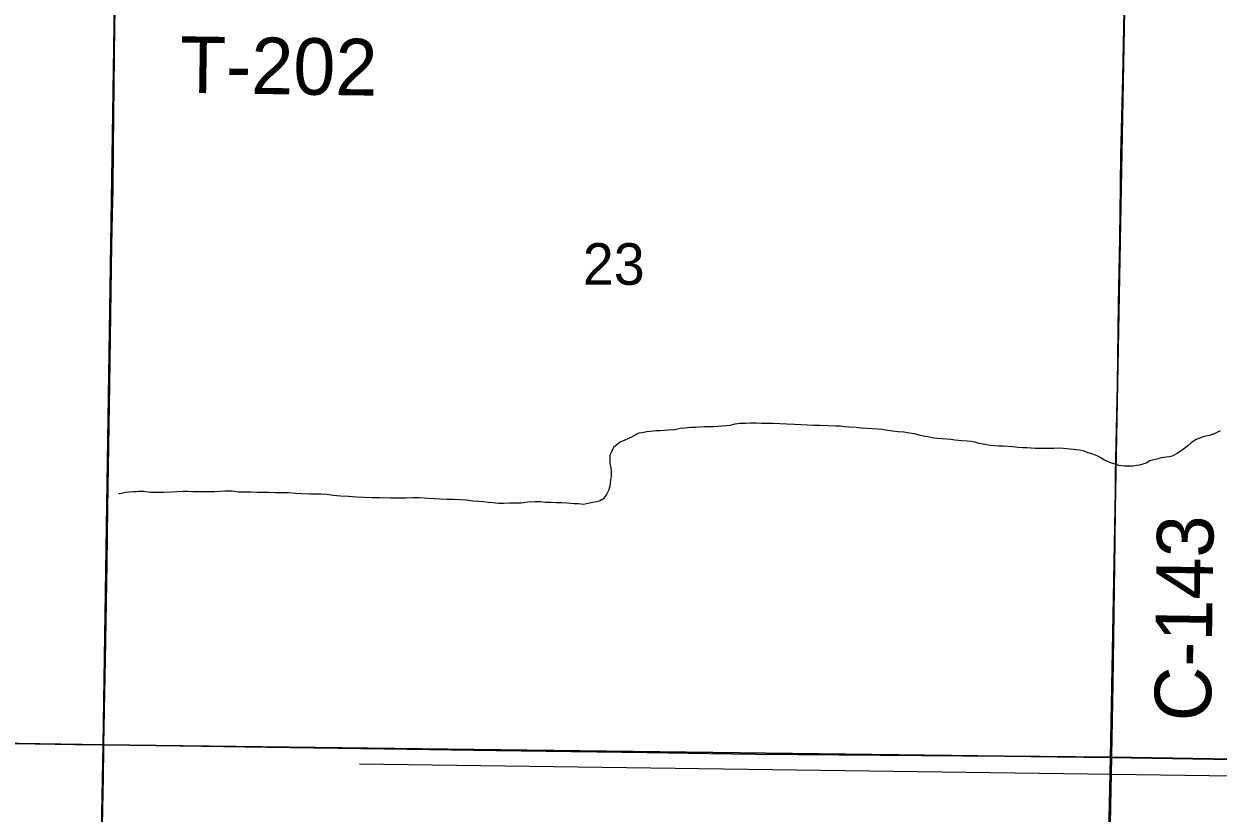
# Model space of a CAD drawing. Extents: x 2.4 to 73.1, y 4.5 to 25.6.
# Drawn here: x 32.442 to 33.042, y 19.564 to 19.96 of the extents above; entities that cross this region are included whole.
import ezdxf

# ---------------------------------------------------------------- set-up
doc = ezdxf.new("R2010")
doc.units = 0
for name, color, linetype in [('GM_X_County_Road', 7, 'Continuous'), ('GM_X_County_Road_Text', 7, 'Continuous'), ('GM_X_Minor_River', 7, 'Continuous'), ('GM_X_Section', 7, 'Continuous'), ('GM_X_Section_Text', 7, 'Continuous'), ('GM_X_State_Route', 7, 'Continuous'), ('GM_X_Township', 7, 'Continuous'), ('GM_X_Township_Road', 7, 'Continuous'), ('GM_X_Township_Road_Text', 7, 'Continuous')]:
    doc.layers.add(name, color=color, linetype=linetype)

msp = doc.modelspace()

# ---------------------------------------------------------------- linework, layer by layer
at = {"layer": 'GM_X_County_Road'}
for points in [[(32.99271, 19.85236), (32.99293, 19.86438), (32.99326, 19.89385), (32.99418, 19.93277), (32.99492, 19.96634)], [(32.98866, 19.59177), (32.98929, 19.62811), (32.99036, 19.69961), (32.99061, 19.73381), (32.99153, 19.77888), (32.99212, 19.8193), (32.99271, 19.85236)]]:
    msp.add_lwpolyline(points, dxfattribs=at)
at = {"layer": 'GM_X_Minor_River'}
for points in [[(32.80994, 19.75946), (32.80709, 19.75947), (32.80442, 19.75929), (32.80195, 19.75929), (32.79929, 19.75892), (32.79682, 19.75836), (32.7951, 19.75817), (32.79282, 19.75799), (32.79073, 19.7578), (32.78845, 19.75762), (32.78617, 19.75763), (32.78408, 19.75763), (32.78179, 19.75745), (32.77951, 19.75727), (32.77704, 19.75727), (32.77438, 19.7569), (32.77172, 19.75672), (32.76905, 19.75615), (32.76582, 19.75597), (32.76392, 19.75579), (32.76183, 19.75561), (32.75992, 19.75561), (32.7584, 19.75542), (32.75669, 19.75524), (32.75498, 19.75505), (32.7527, 19.75468), (32.75099, 19.7545), (32.75003, 19.75393), (32.74737, 19.75241), (32.74623, 19.75185), (32.74337, 19.75053), (32.74185, 19.75015), (32.73823, 19.74731), (32.73709, 19.74465), (32.73651, 19.74332), (32.73651, 19.74085), (32.73651, 19.73895), (32.73688, 19.73705), (32.73707, 19.73553), (32.73706, 19.73287), (32.73687, 19.73078), (32.73668, 19.72945), (32.73648, 19.72774), (32.73591, 19.72603), (32.73496, 19.72394), (32.734, 19.72242), (32.73324, 19.72147), (32.73134, 19.72034), (32.72962, 19.71996), (32.7262, 19.71921), (32.72316, 19.71865), (32.7205, 19.71885), (32.71859, 19.71885), (32.71669, 19.71905), (32.71479, 19.71925), (32.71232, 19.71944), (32.70966, 19.71945), (32.707, 19.71965), (32.70415, 19.71966), (32.70167, 19.71985), (32.69901, 19.71986), (32.69521, 19.71968), (32.69198, 19.71931), (32.68912, 19.71932), (32.68627, 19.71933), (32.68323, 19.71915), (32.68057, 19.71915), (32.67791, 19.71935), (32.67543, 19.71955), (32.67315, 19.71993), (32.67049, 19.72013), (32.66783, 19.72033), (32.66422, 19.72072), (32.66118, 19.72092), (32.65794, 19.72112), (32.65452, 19.72113), (32.65091, 19.72133), (32.64064, 19.72193), (32.6376, 19.72193), (32.6338, 19.72175), (32.62981, 19.72177), (32.62619, 19.72178), (32.62106, 19.72198), (32.61707, 19.72199), (32.61307, 19.72219), (32.60908, 19.7222), (32.60509, 19.7226), (32.6011, 19.7228), (32.59748, 19.72319), (32.59425, 19.72358), (32.59121, 19.72378), (32.58855, 19.72378), (32.5857, 19.72379), (32.58151, 19.72399), (32.57847, 19.72419), (32.57505, 19.72439), (32.57163, 19.7244), (32.5684, 19.72441), (32.56516, 19.72461), (32.56212, 19.72462), (32.55927, 19.72463)], [(33.02972, 19.75047), (33.02838, 19.74934), (33.02686, 19.74801), (33.02553, 19.74706), (33.02458, 19.74631), (33.02362, 19.74555), (33.02267, 19.74498), (33.02153, 19.74422), (33.02039, 19.74347), (33.01906, 19.7429), (33.01772, 19.74252), (33.0162, 19.74234), (33.01487, 19.74215), (33.01354, 19.74197), (33.0124, 19.74178), (33.01126, 19.7414), (33.00974, 19.74103), (33.00783, 19.74046), (33.00593, 19.73933), (33.0027, 19.73839), (33.00117, 19.7382), (33.00022, 19.73801), (32.99927, 19.73783), (32.99794, 19.73783), (32.99642, 19.73783), (32.99509, 19.73784), (32.99357, 19.73803), (32.99224, 19.73823), (32.99091, 19.73861), (32.98977, 19.73899), (32.98768, 19.73976), (32.98616, 19.74033), (32.98483, 19.74091), (32.9835, 19.74186), (32.98198, 19.74263), (32.98046, 19.74339), (32.97875, 19.74397), (32.97685, 19.74454), (32.97476, 19.74531), (32.97248, 19.74588), (32.96449, 19.74667), (32.96202, 19.74686), (32.95955, 19.74668), (32.95746, 19.74669), (32.95537, 19.74669), (32.9529, 19.7467), (32.95023, 19.74671), (32.94795, 19.7469), (32.94605, 19.7471), (32.94396, 19.74711), (32.94168, 19.7473), (32.93883, 19.7475), (32.93655, 19.7477), (32.93407, 19.74789), (32.93198, 19.7479), (32.92989, 19.7481), (32.92761, 19.74829), (32.92571, 19.74849), (32.924, 19.74887), (32.92191, 19.74926), (32.92001, 19.74984), (32.91811, 19.75022), (32.91602, 19.75042), (32.91355, 19.75061), (32.91164, 19.75081), (32.90974, 19.751), (32.90784, 19.7512), (32.90575, 19.7514), (32.90347, 19.75159), (32.90119, 19.75179), (32.89929, 19.75198), (32.89701, 19.75237), (32.89492, 19.75276), (32.89264, 19.75333), (32.8896, 19.7541), (32.88712, 19.75449), (32.88427, 19.75488), (32.88142, 19.75508), (32.87857, 19.75547), (32.87591, 19.75585), (32.87325, 19.75624), (32.87097, 19.75644), (32.8683, 19.75663), (32.86583, 19.75683), (32.86298, 19.75703), (32.86032, 19.75723), (32.85671, 19.75743), (32.85443, 19.75762), (32.85234, 19.75801), (32.85005, 19.75802), (32.84207, 19.75823), (32.83903, 19.75824), (32.8356, 19.75844), (32.83256, 19.75864), (32.82933, 19.75884), (32.82515, 19.75904), (32.82192, 19.75905), (32.81868, 19.75925), (32.81564, 19.75925), (32.8126, 19.75926), (32.80994, 19.75946)], [(33.04323, 19.75557), (33.04018, 19.75406), (33.03771, 19.7533), (33.036, 19.75293), (33.03467, 19.75255), (33.03238, 19.7518), (33.03105, 19.75123), (33.02972, 19.75047)], [(32.55927, 19.72463), (32.55623, 19.72482), (32.553, 19.72483), (32.54976, 19.72484), (32.54672, 19.72523), (32.54292, 19.72524), (32.54045, 19.72506), (32.53797, 19.72488), (32.53512, 19.72488), (32.53227, 19.72489), (32.52961, 19.7249), (32.52695, 19.72491), (32.52448, 19.7251), (32.522, 19.72511), (32.51915, 19.72493), (32.51611, 19.72475), (32.51231, 19.72457), (32.50964, 19.72458), (32.50736, 19.72458), (32.50565, 19.72459), (32.50451, 19.72478), (32.50337, 19.72497), (32.50223, 19.72517), (32.50128, 19.72517), (32.49976, 19.72517), (32.49843, 19.72499), (32.49709, 19.72499), (32.4931, 19.72462), (32.49215, 19.72444), (32.49101, 19.72406), (32.49006, 19.72387), (32.48968, 19.72406), (32.48968, 19.72387)], [(32.61072, 19.58821), (33.48893, 19.57619)]]:
    msp.add_lwpolyline(points, dxfattribs=at)
at = {"layer": 'GM_X_Section'}
for points in [[(31.97801, 20.11054), (32.48953, 20.10156), (32.48193, 19.59785), (31.97137, 19.60585)], [(32.99736, 20.09215), (32.98811, 19.59151), (32.48193, 19.59785), (32.48953, 20.10156)], [(32.99736, 20.09215), (33.49484, 20.08677), (33.49557, 19.58326), (32.98811, 19.59151)], [(32.37206, 19.09708), (32.47209, 19.0957), (32.48193, 19.59785), (31.97137, 19.60585), (31.96815, 19.35283), (32.37206, 19.35283)], [(32.98811, 19.59151), (32.97722, 19.08485), (32.47209, 19.0957), (32.48193, 19.59785)], [(33.49557, 19.58326), (33.48089, 19.0765), (32.97722, 19.08485), (32.98811, 19.59151)]]:
    msp.add_lwpolyline(points, close=True, dxfattribs=at)
at = {"layer": 'GM_X_State_Route'}
for points in [[(32.04183, 19.6043), (32.12111, 19.60322), (32.15219, 19.60274), (32.18017, 19.60232), (32.22694, 19.60163), (32.25478, 19.60122), (32.33716, 19.60001), (32.42732, 19.59865), (32.46773, 19.598), (32.48221, 19.59784), (32.5097, 19.59753), (32.56409, 19.59669), (32.62316, 19.59581), (32.67912, 19.59494), (32.75528, 19.5939), (32.78637, 19.59341), (32.80969, 19.59314), (32.85166, 19.59286), (32.91384, 19.59221), (32.9527, 19.59209), (32.98866, 19.59177)], [(32.97862, 19.08536), (32.9788, 19.09205), (32.98002, 19.14643), (32.98085, 19.19771), (32.98195, 19.24744), (32.98296, 19.30338), (32.98311, 19.31581), (32.98323, 19.33756), (32.98394, 19.37486), (32.98428, 19.3904), (32.98452, 19.40127), (32.98504, 19.41991), (32.98561, 19.43854), (32.98595, 19.44786), (32.98649, 19.47116), (32.98718, 19.50534), (32.98801, 19.55818), (32.98866, 19.59177)], [(32.98866, 19.59177), (33.0393, 19.59088), (33.06574, 19.5904), (33.09373, 19.58991), (33.1575, 19.58894), (33.19637, 19.58828), (33.23681, 19.58762), (33.23772, 19.58761)]]:
    msp.add_lwpolyline(points, dxfattribs=at)
at = {"layer": 'GM_X_Township'}
msp.add_lwpolyline([(32.99481, 19.96661), (32.99406, 19.93305), (32.99314, 19.89412), (32.99281, 19.86465), (32.992, 19.81958), (32.99142, 19.77916), (32.99049, 19.73409), (32.99024, 19.69988), (32.98917, 19.62838), (32.98854, 19.59204), (32.9879, 19.55846)], dxfattribs=at)
at = {"layer": 'GM_X_Township_Road'}
for points in [[(32.48221, 19.59784), (32.48238, 19.60646), (32.48295, 19.64065), (32.48379, 19.68882), (32.48419, 19.71679), (32.48528, 19.77895), (32.4859, 19.82557), (32.48617, 19.84888), (32.48661, 19.86442), (32.48682, 19.87685), (32.48706, 19.8986), (32.4877, 19.95921), (32.488, 19.97503)], [(32.47285, 19.09527), (32.47336, 19.11545), (32.47399, 19.1543), (32.47487, 19.19158), (32.47567, 19.23043), (32.47595, 19.24597), (32.47702, 19.30812), (32.47752, 19.3392), (32.47821, 19.37805), (32.47871, 19.40136), (32.47919, 19.42933), (32.47995, 19.47128), (32.48061, 19.51013), (32.48118, 19.54121), (32.48198, 19.58161), (32.48216, 19.59559), (32.48221, 19.59784)]]:
    msp.add_lwpolyline(points, dxfattribs=at)

# ---------------------------------------------------------------- texts
at = {"layer": 'GM_X_County_Road_Text'}
msp.add_text('C-143', height=0.028409, rotation=89.1736, dxfattribs=at).set_placement((33.03845, 19.60949))
at = {"layer": 'GM_X_Section_Text'}
msp.add_text('23', height=0.020928, rotation=0.00001, dxfattribs=at).set_placement((32.72285, 19.82898))
at = {"layer": 'GM_X_Township_Road_Text'}
msp.add_text('T-202', height=0.028409, rotation=359.15795, dxfattribs=at).set_placement((32.52023, 19.92548))

doc.saveas('drawing.dxf')
